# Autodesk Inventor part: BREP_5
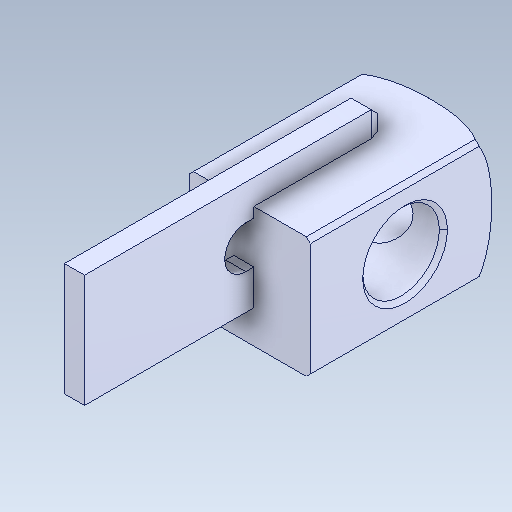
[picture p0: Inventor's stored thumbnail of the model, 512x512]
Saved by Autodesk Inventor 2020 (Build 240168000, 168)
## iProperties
Created: 2017-09
Part Number: BREP_5
Material: Générique
Document SubType Name: Modeling
Designer: bruno
Density: 1 g/cm^3
Appearance: Par défaut
Author: bruno
Sending System: SolidWorks 2016
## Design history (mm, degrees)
feature "Importée1"
node "Solide1"
